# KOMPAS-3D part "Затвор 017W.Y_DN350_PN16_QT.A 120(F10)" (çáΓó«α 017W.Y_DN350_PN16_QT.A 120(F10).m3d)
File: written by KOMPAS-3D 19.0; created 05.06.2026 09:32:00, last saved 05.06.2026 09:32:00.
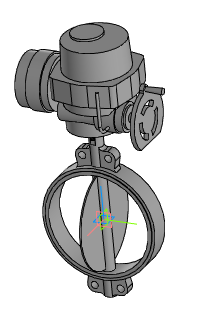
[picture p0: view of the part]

Document properties: Автор: Энергия; Полное имя файла: ..\..\..\3d для проектировщиков\x.x Тип 017W.Y(S) Затвор дисковый поворотный межфланцевый\Затвор 017W.Y(S)_DN32-DN1200_QT.A_MT903.A\Затвор 017W.Y_DN350_PN16_QT.A 120(F10).a3d

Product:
- Part/product: Затвор 017W.Y_DN350_PN16_QT.A 120(F10)
    Масса: 169.59

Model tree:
1. Операция без истории:1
